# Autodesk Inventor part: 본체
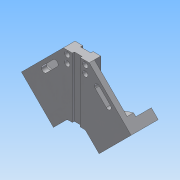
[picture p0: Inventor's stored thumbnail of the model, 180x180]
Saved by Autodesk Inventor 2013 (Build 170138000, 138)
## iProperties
Created: 2019-04
Part Number: 본체
Material: 알루미늄 6061
Document SubType Name: Modeling
Designer: Administrator
Density: 2.71 g/cm^3
Mass: 603.736 g
Surface Area: 426.536 cm^2
Volume: 222.781 cm^3
Author: Administrator
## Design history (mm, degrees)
sketch "스케치3"
  geometry: L1 (0, 0)-(0, -20); L2 (0, -169.706)-(35.355, -134.35); L3 (84.853, -84.853)-(20, -20); L4 (35.355, -134.35)-(14.005, -113); L5 (14.005, -113)-(0, -113); L6 (20, -20)-(0, -20); L7 (0, -113)-(0, -169.706); L8 (35.355, -134.35)-(84.853, -84.853); L9 (0, -20)-(0, -113); L10 (20, -20)-(0, 0)
  constraints: 20 end point, 10 perpendicular, 3 vertical, 2 parallel
  dimensions: "d11" = 45 deg angle of L1 L3; "d12" = 120 distance of L3.start L1.start; "d13" = 50 distance of L2.end L2.start; "d15" = 20 distance from line of L6 L1.start; "d16" = 93 distance between parallel lines of L5 L6
extrude "돌출1" new body sketch "스케치3" distance "d17" = 18; taper "d18" = 0 deg
sketch "스케치4"
  geometry: L1 (-84.853, 84.853)-(-35.355, 134.35) reference; L2 (-35.355, 134.35)-(-14.005, 113) reference; L3 (-14.005, 113)-(0, 113) reference; L4 (0, 113)-(0, 20) reference; L5 (0, 20)-(-20, 20) reference; L6 (-20, 20)-(-84.853, 84.853) reference; L7 (-84.853, 84.853)-(-35.355, 134.35); L8 (-35.355, 134.35)-(-24.749, 123.744); L9 (-24.749, 123.744)-(-74.246, 74.246); L10 (-74.246, 74.246)-(-84.853, 84.853); 1 further point
  constraints: 8 end point, 2 parallel, 2 perpendicular
  dimensions: "d19" = 15 distance between parallel lines of L9 L7
extrude "돌출2" join sketch "스케치4" distance "d21" = 24; taper "d22" = 0 deg
sketch "스케치5"
  geometry: L1 (-84.853, 84.853)-(-35.355, 134.35) reference; L2 (-35.355, 134.35)-(-24.749, 123.744) reference; L3 (-24.749, 123.744)-(-74.246, 74.246) reference; L4 (-20, 20)-(-74.246, 74.246) reference; L5 (0, 20)-(-20, 20) reference; L6 (0, 113)-(0, 20) reference; L7 (-14.005, 113)-(0, 113) reference; L8 (-24.749, 123.744)-(-14.005, 113) reference; L9 (-74.246, 74.246)-(-84.853, 84.853) reference; L10 (-70.711, 70.711)-(-49.497, 77.782); L11 (-49.497, 77.782)-(-20, 48.284); L12 (-20, 48.284)-(-20, 20); L13 (-70.711, 70.711)-(-20, 20); 1 further point
  constraints: 8 end point, 2 parallel, 1 point on line
  dimensions: "d23" = 20 distance from line of L10.start L1; "d24" = 20 distance between parallel lines of L11 L4; "d25" = 90 deg angle of L5 L12; "d26" = 30 distance from line of L10.end L1
extrude "돌출3" cut sketch "스케치5" distance "d27" = 10; taper "d28" = 0 deg
sketch "스케치6"
  geometry: L1 (-35.355, -134.35)-(-84.853, -84.853) reference; L2 (-84.853, -84.853)-(-20, -20) reference; L3 (-20, -20)-(0, -20) reference; L4 (0, -20)-(0, -113) reference; L5 (0, -113)-(-14.005, -113) reference; L6 (-14.005, -113)-(-35.355, -134.35) reference; 3 further points
  constraints: 1 vertical alignment
  dimensions: "d29" = 6 distance from line of L3 point (-14, -26); "d30" = 12 distance of point (-14, -38) point (-14, -26); "d31" = 14 distance from line of L4 point (-14, -26)
hole "구멍1" sketch "스케치6" at (-14, -26), (-14, -38) diameter "d32" = 4.5; stored, may be unused: countersink angle "d36" = 90 deg, drill point angle "d38" = 118 deg; dims "d33" = 6, "d34" = 8, "d35" = 10, "d37" = 8
sketch "스케치7"
  geometry: L1 (-84.853, 84.853)-(-35.355, 134.35) reference; L2 (-35.355, 134.35)-(-14.005, 113) reference; L3 (-14.005, 113)-(0, 113) reference; L4 (0, 113)-(0, 20) reference; L5 (0, 20)-(-20, 20) reference; L6 (-20, 20)-(-70.711, 70.711) reference; L7 (-70.711, 70.711)-(-84.853, 84.853) reference; L8 (-20, 20)-(-20, 48.284) reference; L9 (-20, 48.284)-(-49.497, 77.782) reference; L10 (-49.497, 77.782)-(-70.711, 70.711) reference; L11 (-52.679, 60.458)-(-35.709, 43.487); L12 (-29.345, 49.851)-(-46.315, 66.822); C1 r 4 at (-14, 26) reference; C2 r 4 at (-14, 38) reference; A1 r 4.5 centre (-32.527, 46.669) between (-35.709, 43.487) and (-29.345, 49.851); A2 r 4.5 centre (-49.497, 63.64) between (-46.315, 66.822) and (-52.679, 60.458); 1 further point
  constraints: 4 end point, 4 point on circle, 3 tangent, 2 centre point, 2 parallel
  dimensions: "d39" = 40 distance from line of A2.centre L1; "d41" = 9 distance between parallel lines of L12 L11; "d42" = 10 distance from line of A2.centre L6; "d43" = 10 distance from line of L6 A1.centre; "d44" = 24 distance of L11.start L11.end
extrude "돌출4" cut sketch "스케치7" distance "d45" = 10; taper "d46" = 0 deg
sketch "스케치8"
  geometry: L1 (0, 20)-(0, 113) reference; L2 (0, 113)-(-8, 113); L3 (-8, 113)-(-8, 20); L4 (-8, 20)-(0, 20); L5 (0, 20)-(0, 113); 1 further point
  constraints: 8 end point, 2 parallel, 1 horizontal, 1 perpendicular, 1 point on line
  dimensions: "d47" = 8 distance between parallel lines of L5 L3
extrude "돌출5" cut sketch "스케치8" distance "d49" = 3.5; taper "d50" = 0 deg
sketch "스케치9"
  geometry: L1 (0, -20)-(0, -113) reference; L2 (0, -20)-(-6, -20); L3 (-6, -20)-(-6, -113); L4 (-6, -113)-(0, -113); L5 (0, -113)-(0, -20); 1 further point
  constraints: 8 end point, 2 parallel, 1 horizontal, 1 perpendicular, 1 point on line
  dimensions: "d51" = 6 distance of L1.start L2.end
extrude "돌출6" cut sketch "스케치9" distance "d52" = 3; taper "d53" = 0 deg
fillet "모깎기1" dims "d54" = 5
sketch "스케치10"
  geometry: L1 (-35.355, 134.35)-(-84.853, 84.853) reference; L2 (-24.749, 123.744)-(-35.355, 134.35) reference; 2 further points
  constraints: 1 other
  dimensions: "d56" = 35 distance from line of L2 point (-54.801, 104.298); "d57" = 7.5 distance from line of L1 point (-54.801, 104.298)
feature "엠보싱1" sketch "스케치10" dims "d11" = 45 deg, "d12" = 120, "d13" = 50, "d15" = 20, "d16" = 93, "d58" = 0.5, "d59" = 0
node "솔리드1"
mirror "대칭1"
node "절단 모서리 투영1"
node "절단 모서리 투영2"
node "절단 모서리 투영3"
node "절단 모서리 투영4"
